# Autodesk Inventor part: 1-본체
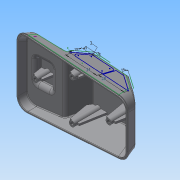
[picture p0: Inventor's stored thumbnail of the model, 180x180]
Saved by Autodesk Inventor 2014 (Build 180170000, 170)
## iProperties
Created: 2015-05
Part Number: 1-본체
Material: Generic
Document SubType Name: Modeling
Designer: Administrator
Density: 1 g/cm^3
Appearance: Default
Author: Administrator
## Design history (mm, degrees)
sketch "스케치1"
  geometry: L1 (-61, 0)-(61, 0); L2 (61, 0)-(58.321, 10); L3 (58.321, 10)-(31, 30); L4 (31, 30)-(-7.174, 30); L5 (-7.174, 30)-(-19, 11.075); L6 (-19, 11.075)-(-58.588, 9); L7 (-58.588, 9)-(-61, 0); 2 further points
  constraints: 14 end point, 2 coincident, 1 horizontal, 1 midpoint, 1 parallel
  dimensions: "d0" = 122 distance of L1.start L1.end; "d1" = 105 deg angle of L1 L2; "d2" = 20 distance from line of L2.end L4; "d3" = 30 distance between parallel lines of L1 L4; "d4" = 30 horizontal distance of L1.end L3.end; "d5" = 42 horizontal distance of L5.end L1.start; "d6" = 125 deg angle of L5 L6; "d7" = 105 deg angle of L1 L7; "d8" = 3 deg angle of L1 L6; "d9" = 9 vertical distance of L1.start L6.end
extrude "돌출1" new body sketch "스케치1" stored distance "d10" = 76; taper "d11" = 0 deg
sketch "스케치13"
  geometry: L1 (76, 0)-(0, 0) reference; L2 (0, 21.568)-(0, 42.909) reference; L3 (76, 42.909)-(76, 21.568) reference; L4 (0, 52.789)-(76, 52.789) reference; L5 (76, 0)-(61.855, 52.789); L6 (0, 0)-(14.145, 52.789); L7 (0, 0)-(0, 52.789); L8 (76, 52.789)-(76, 0); 1 further point
  constraints: 8 end point, 2 point on line, 1 parallel, 1 perpendicular
  dimensions: "d146" = 105 deg angle of L1 L5; "d147" = 105 deg angle of L1 L6
extrude "돌출15" cut sketch "스케치13" stored distance "d148" = 2; taper "d149" = 0 deg
fillet "모깎기2" dims "d17" = 12
fillet "모깎기3" dims "d19" = 3
fillet "모깎기7" dims "d150" = 3
fillet "모깎기8" dims "d151" = 3
node "작업 평면3"
sketch "스케치6"
  geometry: L1 (-50, 9.394)-(-48.458, 14.538); L2 (-48.458, 14.538)-(-32.098, 15.395); L3 (-32.098, 15.395)-(-30, 10.452); L4 (50.184, 0)-(-48.577, 0) reference; L5 (-48.577, 0)-(-61, 0) reference; L6 (-20.56, 10.993)-(-46.962, 9.609) reference; L7 (-56.412, 9.114)-(-46.962, 9.609) reference; L8 (-50, 9.394)-(-30, 10.452); 1 further point
  constraints: 8 end point, 1 coincident, 1 equal length
  dimensions: "d120" = 20 horizontal distance of L3.end L1.start; "d152" = 11 horizontal distance of L1.start point (-61, 0); "d153" = 5 distance between parallel lines of L6 L2; "d154" = 70 deg angle of L6 L3; "d155" = 73.3088 deg angle of L4 L1; "d156" = 69.7262 distance from line of L4.start L3
extrude "돌출16" join sketch "스케치6" distance "d157" = 26; taper "d158" = 0 deg
fillet "모깎기6" dims "d123" = 3
fillet "모깎기5" dims "d45" = 3
feature "쉘1" dims "d12" = 2
sketch "스케치14"
  geometry: L1 (12.423, 60.645)-(110.916, 53.814) reference; L2 (119.929, 44.176)-(119.929, 6.977) reference; L3 (110.916, -2.661)-(12.423, -9.491) reference; L4 (2.071, 0.144)-(2.071, 51.01) reference; L5 (111.184, 55.866)-(12.423, 62.715) reference; L6 (110.99, 54.877)-(12.497, 61.708); L7 (1.005, 51.01)-(1.005, 0.144); L8 (12.497, -10.554)-(110.99, -3.724); L9 (120.995, 6.977)-(120.995, 44.176); 5 further points; 4 other entities
  constraints: 8 end point, 7 parallel, 16 other
  dimensions: "d170" = 1 distance between parallel lines of L6 L5
extrude "돌출17" join sketch "스케치14" distance "d171" = 1; taper "d172" = 0 deg
node "작업 평면2"
sketch "스케치15"
  geometry: L1 (122, 6.853)-(122, 44.3) reference; C1 r 3 at (21, 25.577); C2 r 3 at (101, 25.577); C3 r 3 at (61, 3.577); C4 r 3 at (61, 47.577); 1 further point
  constraints: 4 centre point, 3 equal radius, 2 horizontal alignment, 2 vertical alignment
  dimensions: "d173" = 44 distance of C4.centre C3.centre; "d174" = 22 distance of C3.centre point (61, 25.577); "d175" = 21 distance from line of L1 C2.centre; "d176" = 40 distance of point (61, 25.577) C1.centre; "d177" = 6 diameter of C2
extrude "돌출18" join sketch "스케치15" stored distance "d178" = 1; taper "d179" = 0 deg
sketch "스케치4"
  geometry: L1 (-37, 0)-(-37, 13.136) reference; L2 (-43, 0)-(-43, 12.821) reference; L3 (37, 0)-(37, 23.129) reference; L4 (43, 0)-(43, 18.737) reference; L5 (37, 0)-(36.939, 1.753); L6 (36.939, 1.753)-(35, 1.753); L7 (35, 1.753)-(30.019, 30); L8 (43, 0)-(43.061, 1.753); L9 (43.061, 1.753)-(45, 1.753); L10 (45, 1.753)-(47.811, 17.694); L11 (-37, 0)-(-36.93, 2); L12 (-36.93, 2)-(-35, 2); L13 (-35, 2)-(-32.945, 13.652); L14 (-43, 0)-(-43.07, 2); L15 (-43.07, 2)-(-45, 2); L16 (-45, 2)-(-47.222, 14.603); L17 (-36.096, 15.186)-(-47.539, 14.586) reference; L18 (45.877, 19.109)-(57.468, 10.624) reference; L19 (45.877, 19.109)-(31.791, 29.421) reference; L20 (48.577, 0)-(-50.184, 0) reference; L21 (-43, 0)-(-37, 0); L22 (37, 0)-(43, 0); L23 (-47.222, 14.603)-(-35.732, 15.205); L24 (47.811, 17.694)-(31.791, 29.421); A1 r 3 centre (-47.745, 11.571) between (-47.902, 14.567) and (-50.614, 12.448) reference; A2 r 3 centre (-35.575, 12.209) between (-32.814, 13.381) and (-35.732, 15.205) reference; A3 r 3 centre (30.019, 27) between (31.791, 29.421) and (30.019, 30) reference; A4 r 3 centre (-35.575, 12.209) between (-32.945, 13.652) and (-35.732, 15.205); 3 further points; 1 other entity
  constraints: 33 end point, 5 collinear, 4 equal length, 3 point on circle, 3 tangent, 2 parallel, 2 point on line, 1 centre point, 1 perpendicular, 2 other
  dimensions: "d55" = 10 distance of L6.end L9.end; "d56" = 10 deg angle of L3 L7; "d57" = 10 deg angle of L10 L4; "d59" = 2 deg angle of L11 L1; "d60" = 2 deg angle of L2 L14; "d62" = 10 distance of L12.end L15.end; "d63" = 10 deg angle of L2 L16; "d66" = 4 deg angle of L8 L5; "d125" = 2 distance between parallel lines of L20 L12
extrude "돌출12" join sketch "스케치4" stored distance "d127" = 2; taper "d128" = 0 deg
extrude "돌출13" join sketch "스케치4" stored distance "d129" = 2; taper "d130" = 0 deg
node "작업 평면4"
sketch "스케치7"
  geometry: L1 (-3, 0)-(-3, 28) reference; L2 (3, 0)-(3, 28) reference; L3 (3, 0)-(3.07, 2); L4 (3.07, 2)-(5, 2); L5 (-3, 0)-(-3.07, 2); L6 (-3.07, 2)-(-5, 2); L7 (-5, 2)-(-9.329, 26.551); L8 (5, 2)-(9.937, 30); L9 (48.577, 0)-(-50.184, 0) reference; L10 (-3, 0)-(3, 0); L11 (30.019, 30)-(-5.511, 30) reference; L12 (-8.055, 28.59)-(-18.172, 12.399) reference; L13 (-9.329, 26.551)-(-8.055, 28.59); L14 (-5.511, 30)-(9.937, 30); A1 r 3 centre (-5.511, 27) between (-5.511, 30) and (-8.055, 28.59) reference; A2 r 3 centre (-5.511, 27) between (-5.511, 30) and (-8.055, 28.59); 1 further point
  constraints: 18 end point, 3 point on circle, 2 collinear, 2 equal length, 2 tangent, 1 centre point, 1 concentric
  dimensions: "d75" = 2 deg angle of L1 L5; "d76" = 2 deg angle of L3 L2; "d78" = 10 distance of L4.end L6.end; "d79" = 10 deg angle of L2 L8; "d80" = 10 deg angle of L7 L1; "d131" = 2 distance between parallel lines of L9 L4; "d132" = 30 distance from line of L8.end L9; "d133" = 26.55145 distance from line of L7.end L9
extrude "돌출14" join sketch "스케치7" stored distance "d134" = 2; taper "d135" = 0 deg
sketch "스케치8"
  geometry: L1 (110.916, 53.814)-(12.423, 60.645) reference; L2 (2.071, 51.01)-(2.071, 0.144) reference; L3 (12.423, -9.491)-(110.916, -2.661) reference; L4 (119.929, 6.977)-(119.929, 44.176) reference; L5 (120.995, 44.176)-(120.995, 6.977) reference; L6 (110.99, -3.724)-(12.497, -10.554) reference; L7 (1.005, 0.144)-(1.005, 51.01) reference; L8 (12.497, 61.708)-(110.99, 54.877) reference; C1 r 3 at (61, 3.577) reference; C2 r 3 at (21, 25.577) reference; C3 r 3 at (101, 25.577) reference; C4 r 3 at (61, 47.577) reference; 8 further points; 4 other entities
  constraints: 4 coincident, 8 other
hole "구멍2" sketch "스케치8" at (21, 25.577), (61, 47.577), (101, 25.577), (61, 3.577) diameter "d180" = 3.242; stored, may be unused: countersink angle "d184" = 90 deg, drill point angle "d186" = 118 deg; dims "d181" = 9, "d182" = 4, "d183" = 2, "d185" = 11
sketch "스케치16"
  geometry: L1 (2.11, 7.605)-(24.946, 8.837) reference; L2 (0, 0)-(2.11, 7.605) reference; L3 (98.998, 0)-(0, 0) reference; L4 (94.902, 16.876)-(98.998, 0) reference; L5 (79.483, 28.66)-(94.902, 16.876) reference; L6 (43.867, 28.66)-(79.483, 28.66) reference; L7 (33.436, 11.938)-(43.867, 28.66); L8 (78.785, 26.565)-(98.412, 11.565); L9 (3.518, 2.675)-(4.174, 5.037); L10 (38.432, 16.153)-(44.047, 25.153); L11 (46.592, 26.565)-(66.57, 26.565); L12 (40.978, 11.565)-(66.57, 11.565); L13 (69.57, 23.565)-(69.57, 14.565); L14 (59.158, 31.565)-(43.867, 31.565) reference; L15 (41.329, 30.243)-(30.898, 13.522) reference; L16 (96.67, 19.19)-(81.251, 30.973) reference; L17 (98.412, 11.565)-(70.412, 11.565); L18 (70.412, 11.565)-(70.412, 26.565); L19 (78.785, 26.565)-(70.412, 26.565); A1 r 3 centre (46.592, 23.565) between (46.592, 26.565) and (44.047, 25.153); A2 r 3 centre (40.978, 14.565) between (38.432, 16.153) and (40.978, 11.565); A3 r 3 centre (66.57, 14.565) between (66.57, 11.565) and (69.57, 14.565); A4 r 3 centre (66.57, 23.565) between (69.57, 23.565) and (66.57, 26.565); 5 further points; 1 other entity
  constraints: 20 end point, 8 point on circle, 8 tangent, 6 point on line, 4 centre point, 3 equal radius, 3 perpendicular, 2 parallel, 2 other
  dimensions: "d190" = 34 distance of point (69.57, 11.565) point (35.57, 11.565); "d191" = 5 distance between parallel lines of L11 L14; "d192" = 15 distance between parallel lines of L12 L11; "d193" = 5 distance between parallel lines of L15 L10; "d194" = 5 distance between parallel lines of L16 L8; "d195" = 3 radius of A1; "d196" = 28 distance of L8.end L17.end
sketch "스케치10"
  geometry: A1 r 4 centre (5, 0) between (9, 0) and (1, 0); A2 r 4 centre (16, 0) between (20, 0) and (12, 0); A3 r 4 centre (36, 0) between (40, 0) and (32, 0); A4 r 4 centre (47, 0) between (51, 0) and (43, 0); 5 further points
  constraints: 8 point on circle, 4 centre point, 3 equal radius, 13 other
  dimensions: "d100" = 11 distance of A2.centre A1.centre; "d101" = 20 distance of A3.centre A2.centre; "d102" = 11 distance of A4.centre A3.centre; "d103" = 4 radius of A2; "d104" = 10 horizontal distance of point (26, 15.788) A2.centre
extrude "돌출10" join sketch "스케치10" distance "d105" = 2; taper "d106" = 0 deg
sketch "스케치11"
  geometry: L1 (66.511, 53.724)-(66.511, 16.276) reference; 6 further points
  constraints: 1 horizontal alignment, 1 other
  dimensions: "d107" = 50 distance from line of point (16.511, 35) L1
feature "엠보싱1" sketch "스케치11" dims "d108" = 0.5, "d109" = 0
node "솔리드1"
mirror "대칭1"
mirror "대칭2"
node "절단 모서리 투영5"
other parameters: "d30" = 13, "d37" = 13, "d74" = 22
